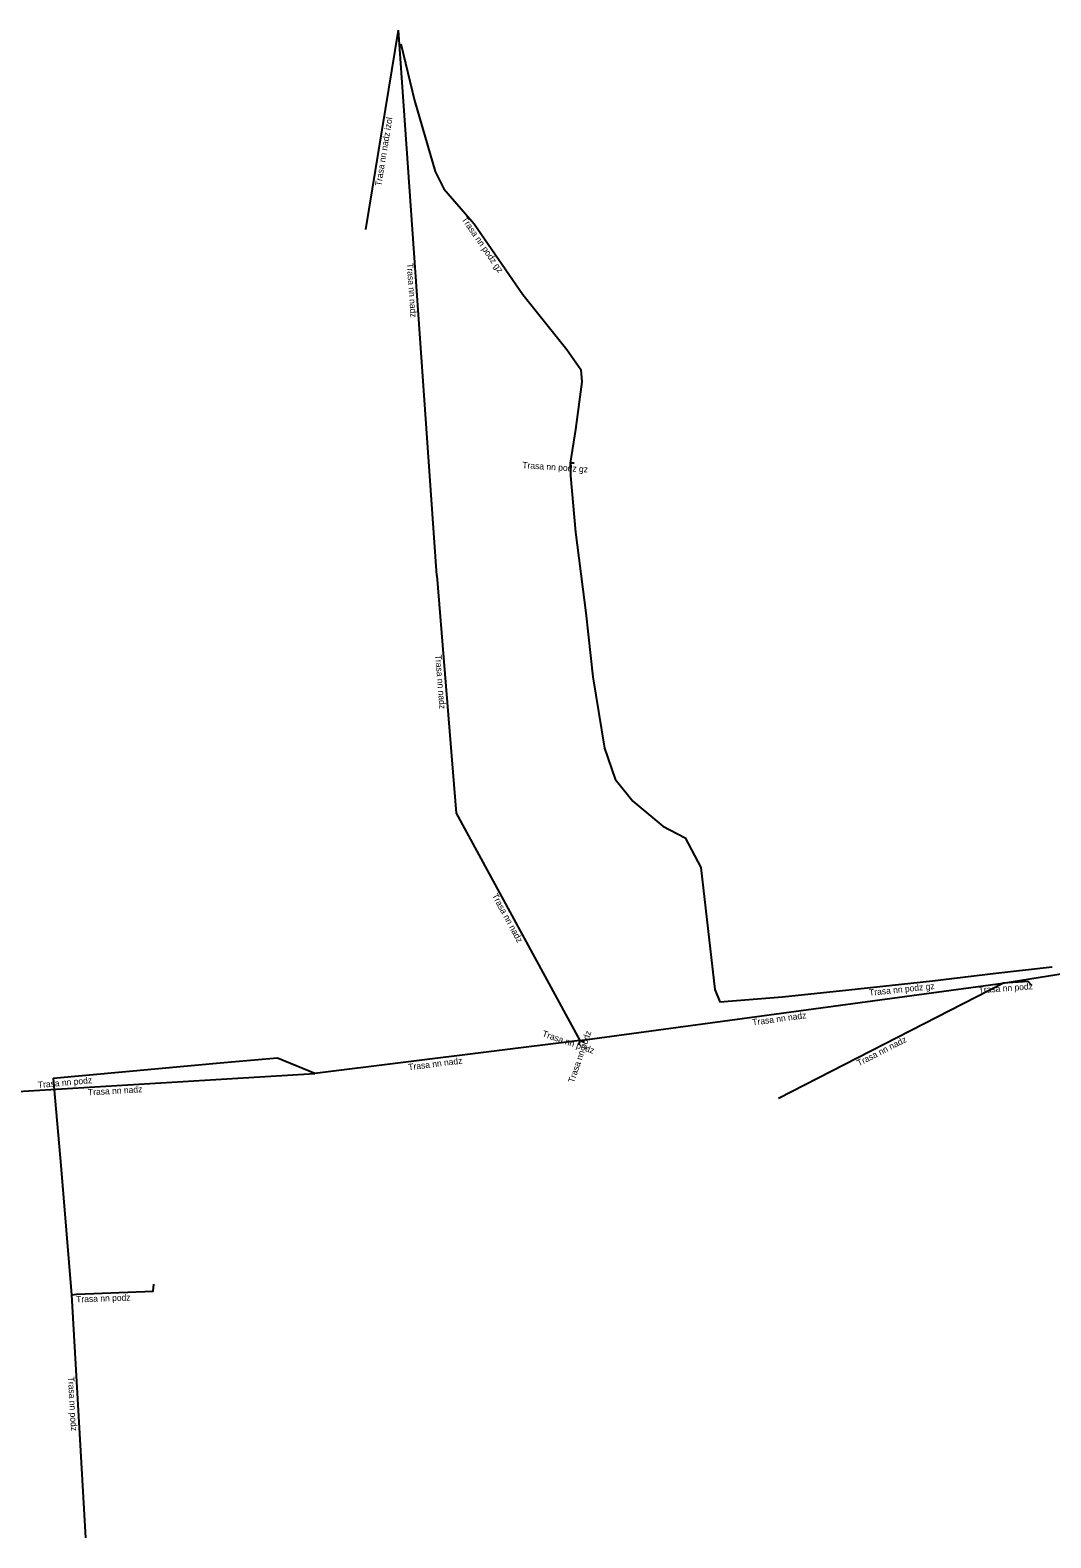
# Model space of a CAD drawing. Extents: x -682605 to -681948, y -1059884 to -1059661.
# Drawn here: x -682220.9 to -682140.7, y -1059831.6 to -1059713.2 of the extents above; entities that cross this region are included whole.
import ezdxf

# ---------------------------------------------------------------- set-up
doc = ezdxf.new("R2010")
doc.units = 0
doc.layers.add('Popiskový text - Ostatní atributy Trasy', color=7, linetype='Continuous')
doc.layers.add('Spojnice NN', color=7, linetype='Continuous')

msp = doc.modelspace()

# ---------------------------------------------------------------- linework, layer by layer
at = {"layer": 'Spojnice NN'}
for points in [[(-682194.5, -1059728.84), (-682191.92, -1059713.17)], [(-682188.9, -1059756.02), (-682191.92, -1059713.17)], [(-682191.74, -1059714.25), (-682190.66, -1059718.7), (-682189.04, -1059724.27), (-682188.36, -1059725.65), (-682185.97, -1059728.38), (-682182.14, -1059733.93), (-682178.68, -1059738.27), (-682177.6, -1059739.84), (-682177.5, -1059740.81), (-682178.01, -1059744.56), (-682178.42, -1059747.18)], [(-682178.12, -1059747.2), (-682178.42, -1059747.18)], [(-682178.42, -1059747.18), (-682178.39, -1059748.18), (-682178.01, -1059752.62), (-682177.2, -1059758.95), (-682176.65, -1059763.97), (-682175.73, -1059769.58), (-682174.89, -1059772.03), (-682173.5, -1059773.75), (-682171.15, -1059775.71), (-682169.39, -1059776.63), (-682168.15, -1059778.96), (-682167.07, -1059788.54), (-682166.66, -1059789.52), (-682161.75, -1059789.13), (-682156.53, -1059788.56), (-682149.95, -1059787.87), (-682144.97, -1059787.26), (-682140.54, -1059786.75)], [(-682188.9, -1059756.02), (-682187.38, -1059774.68)], [(-682187.38, -1059774.68), (-682177.66, -1059792.56)], [(-682144.43, -1059788.05), (-682084.21, -1059778.39)], [(-682177.66, -1059792.56), (-682144.43, -1059788.05)], [(-682162.05, -1059797.07), (-682144.43, -1059788.05)], [(-682142.16, -1059788.24), (-682142.44, -1059787.9), (-682144.43, -1059788.05)], [(-682177.66, -1059792.56), (-682198.49, -1059795.15)], [(-682177.66, -1059792.56), (-682177.78, -1059792.91)], [(-682177.66, -1059792.56), (-682177.29, -1059792.68)], [(-682198.49, -1059795.15), (-682201.43, -1059793.93), (-682205.66, -1059794.29), (-682219.07, -1059795.53), (-682218.47, -1059802.37), (-682217.62, -1059812.54)], [(-682227.92, -1059796.92), (-682198.49, -1059795.15)], [(-682217.62, -1059812.54), (-682217.21, -1059812.48), (-682211.19, -1059812.25), (-682211.16, -1059811.68)], [(-682217.62, -1059812.54), (-682216.52, -1059831.62)]]:
    msp.add_lwpolyline(points, dxfattribs=at)

# ---------------------------------------------------------------- texts
at = {"layer": 'Popiskový text - Ostatní atributy Trasy'}
for s, rotation, p in [('Trasa nn nadz izol', 80.632, (-682193.28, -1059725.45)), ('Trasa nn podz gz', 304.6092, (-682186.99, -1059728.04)), ('Trasa nn nadz', 274.032, (-682191.27, -1059731.5)), ('Trasa nn podz gz', 356.1859, (-682182.2, -1059747.58)), ('Trasa nn nadz', 274.6322, (-682189.04, -1059762.26)), ('Trasa nn nadz', 298.5311, (-682184.6, -1059781.16)), ('Trasa nn podz gz', 5.9863, (-682154.91, -1059789.04)), ('Trasa nn podz', 4.2756, (-682146.31, -1059788.84)), ('Trasa nn nadz', 7.7213, (-682164.08, -1059791.37)), ('Trasa nn podz', 341.0556, (-682180.67, -1059792.21)), ('Trasa nn podz', 71.1255, (-682178.13, -1059795.92)), ('Trasa nn nadz', 27.1229, (-682155.74, -1059794.58)), ('Trasa nn nadz', 7.1, (-682191.12, -1059794.89)), ('Trasa nn podz', 5.283, (-682220.24, -1059796.29)), ('Trasa nn nadz', 3.4418, (-682216.31, -1059796.87)), ('Trasa nn podz', 2.158, (-682217.24, -1059813.13)), ('Trasa nn podz', 273.2996, (-682217.9, -1059818.97))]:
    msp.add_text(s, height=0.5, rotation=rotation, dxfattribs=at).set_placement(p)

doc.saveas('drawing.dxf')
